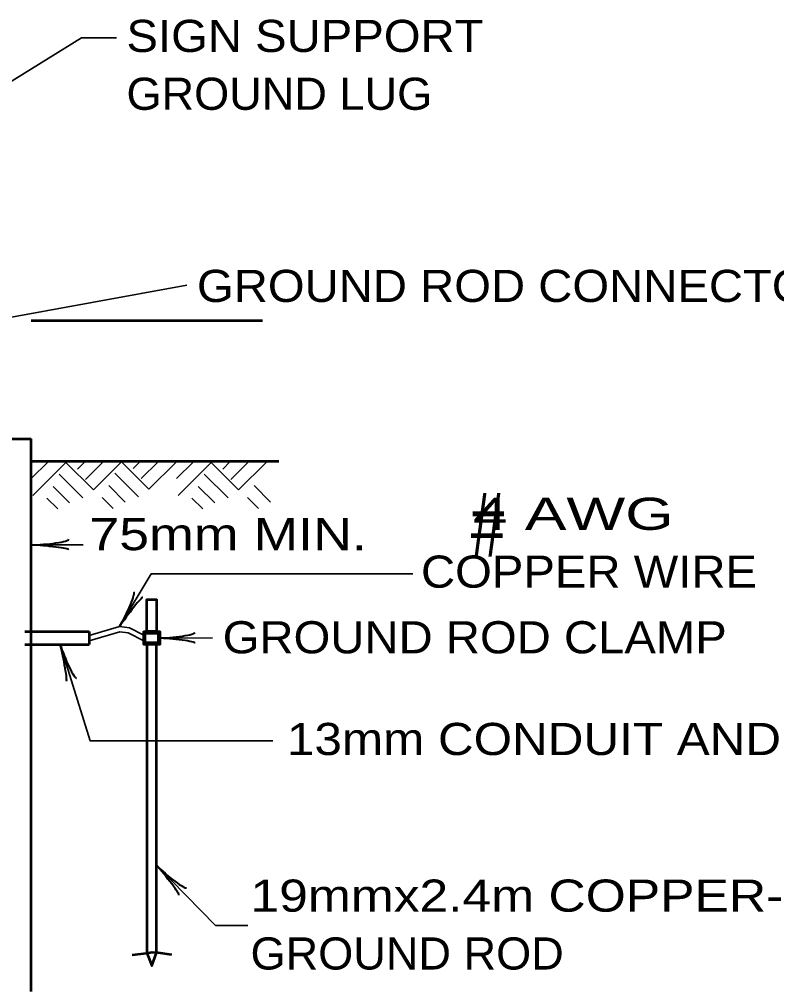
# Model space of a CAD drawing. Extents: x -111 to 744, y -77 to 467.
# Drawn here: x 250.1 to 320.8, y 162.4 to 252.8 of the extents above; entities that cross this region are included whole.
import ezdxf

# ---------------------------------------------------------------- set-up
doc = ezdxf.new("R2010")
doc.units = 0
doc.header["$LTSCALE"] = 1.2
doc.linetypes.add('LONG_DASHED', pattern=[7.5, 6, -1.5])
doc.layers.add('1', color=7, linetype='Continuous', lineweight=53)

msp = doc.modelspace()

# ---------------------------------------------------------------- linework, layer by layer
at = {"layer": '1', "lineweight": 35}
for p, q in [((234.019, 222.168), (265.782, 227.964)), ((252.823, 211.483), (251.239, 209.899)), ((254.527, 211.483), (251.383, 208.339)), ((254.407, 211.483), (257.047, 208.843)), ((256.231, 211.483), (255.559, 210.787)), ((257.959, 211.483), (256.303, 209.827)), ((259.663, 211.483), (257.047, 208.843)), ((259.663, 211.483), (262.231, 208.915)), ((261.367, 211.483), (260.743, 210.859)), ((263.095, 211.483), (261.511, 209.899)), ((264.799, 211.483), (262.231, 208.915)), ((266.383, 211.483), (264.799, 209.899)), ((268.087, 211.483), (264.943, 208.339)), ((267.967, 211.483), (270.607, 208.843)), ((269.791, 211.483), (269.119, 210.787)), ((271.519, 211.483), (269.863, 209.827)), ((273.223, 211.483), (270.607, 208.843)), ((253.831, 210.331), (256.063, 208.123)), ((259.039, 210.403), (261.247, 208.195)), ((267.391, 210.331), (269.623, 208.123)), ((253.279, 209.179), (254.815, 207.643)), ((258.487, 209.251), (260.023, 207.715)), ((266.839, 209.179), (268.375, 207.643)), ((272.047, 209.251), (273.583, 207.715)), ((252.679, 208.075), (253.711, 207.067)), ((257.863, 208.147), (258.895, 207.115)), ((266.239, 208.075), (267.271, 207.067)), ((271.423, 208.147), (272.455, 207.115)), ((251.289, 203.717), (256.089, 203.717)), ((263.089, 195.018), (268.156, 195.032))]:
    msp.add_line(p, q, dxfattribs=at)
at = {"layer": '1'}
for p, q in [((251.239, 224.648), (272.839, 224.648)), ((251.239, 162.031), (251.239, 213.618)), ((251.239, 211.531), (274.358, 211.531)), ((251.239, 195.618), (256.639, 195.618)), ((256.639, 195.618), (256.639, 194.418)), ((261.739, 195.603), (261.754, 195.618)), ((261.739, 195.586), (261.771, 195.618)), ((261.739, 195.569), (261.788, 195.618)), ((261.739, 195.552), (261.805, 195.618)), ((261.739, 195.535), (261.822, 195.618)), ((261.739, 195.518), (261.839, 195.618)), ((261.739, 195.501), (261.856, 195.618)), ((261.739, 195.484), (261.873, 195.618)), ((261.739, 195.467), (261.89, 195.618)), ((261.739, 195.45), (261.907, 195.618)), ((261.739, 195.433), (261.924, 195.618)), ((261.739, 195.416), (261.941, 195.618)), ((261.739, 195.399), (261.958, 195.618)), ((261.739, 195.382), (261.975, 195.618)), ((261.739, 195.365), (261.992, 195.618)), ((261.739, 195.348), (262.009, 195.618)), ((261.739, 195.331), (262.026, 195.618)), ((261.739, 195.314), (261.889, 195.464)), ((261.739, 195.297), (261.889, 195.447)), ((261.739, 195.28), (261.889, 195.43)), ((261.739, 195.263), (261.889, 195.413)), ((261.739, 195.246), (261.889, 195.396)), ((261.739, 195.229), (261.889, 195.379)), ((261.739, 195.213), (261.889, 195.363)), ((261.739, 195.196), (261.889, 195.346)), ((261.739, 195.179), (261.889, 195.329)), ((261.739, 195.162), (261.889, 195.312)), ((261.739, 195.145), (261.889, 195.295)), ((261.739, 195.128), (261.889, 195.278)), ((261.739, 195.111), (261.889, 195.261)), ((261.889, 195.468), (262.039, 195.468)), ((261.893, 195.468), (262.043, 195.618)), ((261.91, 195.468), (262.06, 195.618)), ((261.927, 195.468), (262.077, 195.618)), ((261.944, 195.468), (262.094, 195.618)), ((261.961, 195.468), (262.111, 195.618)), ((261.978, 195.468), (262.128, 195.618)), ((261.995, 195.468), (262.145, 195.618)), ((262.012, 195.468), (262.162, 195.618)), ((262.029, 195.468), (262.179, 195.618)), ((262.039, 195.618), (262.939, 195.618)), ((262.046, 195.468), (262.196, 195.618)), ((262.062, 195.468), (262.213, 195.618)), ((262.079, 195.468), (262.23, 195.618)), ((262.096, 195.468), (262.247, 195.618)), ((262.113, 195.468), (262.263, 195.618)), ((262.13, 195.468), (262.28, 195.618)), ((262.147, 195.468), (262.297, 195.618)), ((262.164, 195.468), (262.314, 195.618)), ((262.181, 195.468), (262.331, 195.618)), ((262.198, 195.468), (262.348, 195.618)), ((262.215, 195.468), (262.365, 195.618)), ((262.232, 195.468), (262.382, 195.618)), ((262.249, 195.468), (262.399, 195.618)), ((262.266, 195.468), (262.416, 195.618)), ((262.283, 195.468), (262.433, 195.618)), ((262.3, 195.468), (262.45, 195.618)), ((262.317, 195.468), (262.467, 195.618)), ((262.334, 195.468), (262.484, 195.618)), ((262.351, 195.468), (262.501, 195.618)), ((262.368, 195.468), (262.518, 195.618)), ((262.385, 195.468), (262.535, 195.618)), ((262.402, 195.468), (262.552, 195.618)), ((262.419, 195.468), (262.569, 195.618)), ((262.436, 195.468), (262.586, 195.618)), ((262.453, 195.468), (262.603, 195.618)), ((262.47, 195.468), (262.62, 195.618)), ((262.487, 195.468), (262.637, 195.618)), ((262.504, 195.468), (262.654, 195.618)), ((262.521, 195.468), (262.671, 195.618)), ((262.538, 195.468), (262.688, 195.618)), ((262.555, 195.468), (262.705, 195.618)), ((262.572, 195.468), (262.722, 195.618)), ((262.589, 195.468), (262.739, 195.618)), ((262.606, 195.468), (262.756, 195.618)), ((262.623, 195.468), (262.773, 195.618)), ((262.639, 195.468), (262.79, 195.618)), ((262.656, 195.468), (262.807, 195.618)), ((262.673, 195.468), (262.824, 195.618)), ((262.69, 195.468), (262.84, 195.618)), ((262.707, 195.468), (262.857, 195.618)), ((262.724, 195.468), (262.874, 195.618)), ((262.741, 195.468), (262.891, 195.618)), ((262.758, 195.468), (262.908, 195.618)), ((262.775, 195.468), (262.925, 195.618)), ((262.792, 195.468), (262.942, 195.618)), ((262.809, 195.468), (262.959, 195.618)), ((262.826, 195.468), (262.976, 195.618)), ((262.843, 195.468), (262.993, 195.618)), ((262.86, 195.468), (263.01, 195.618)), ((262.877, 195.468), (263.027, 195.618)), ((262.894, 195.468), (263.044, 195.618)), ((262.911, 195.468), (263.061, 195.618)), ((262.928, 195.468), (263.078, 195.618)), ((262.945, 195.468), (263.095, 195.618)), ((262.962, 195.468), (263.112, 195.618)), ((262.979, 195.468), (263.129, 195.618)), ((262.996, 195.468), (263.146, 195.618)), ((263.013, 195.468), (263.163, 195.618)), ((263.03, 195.468), (263.18, 195.618)), ((263.047, 195.468), (263.197, 195.618)), ((263.064, 195.468), (263.214, 195.618)), ((263.081, 195.468), (263.231, 195.618)), ((263.089, 195.459), (263.239, 195.609)), ((263.089, 195.442), (263.239, 195.592)), ((263.089, 195.425), (263.239, 195.575)), ((263.089, 195.409), (263.239, 195.559)), ((263.089, 195.392), (263.239, 195.542)), ((263.089, 195.375), (263.239, 195.525)), ((263.089, 195.358), (263.239, 195.508)), ((263.089, 195.341), (263.239, 195.491)), ((263.089, 195.324), (263.239, 195.474)), ((263.089, 195.307), (263.239, 195.457)), ((263.089, 195.29), (263.239, 195.44)), ((263.089, 195.273), (263.239, 195.423)), ((263.089, 195.256), (263.239, 195.406)), ((263.089, 195.239), (263.239, 195.389)), ((263.089, 195.222), (263.239, 195.372)), ((263.089, 195.205), (263.239, 195.355)), ((263.089, 195.188), (263.239, 195.338)), ((263.089, 195.171), (263.239, 195.321)), ((263.089, 195.154), (263.239, 195.304)), ((263.089, 195.137), (263.239, 195.287)), ((263.089, 195.12), (263.239, 195.27)), ((263.089, 195.103), (263.239, 195.253)), ((251.239, 194.418), (256.639, 194.418)), ((261.739, 195.094), (261.889, 195.244)), ((261.739, 195.077), (261.889, 195.227)), ((261.739, 195.06), (261.889, 195.21)), ((261.739, 195.043), (261.889, 195.193)), ((261.739, 195.026), (261.889, 195.176)), ((261.739, 195.009), (261.889, 195.159)), ((261.739, 194.992), (261.889, 195.142)), ((261.739, 194.975), (261.889, 195.125)), ((261.739, 194.958), (261.889, 195.108)), ((261.739, 194.941), (261.889, 195.091)), ((261.739, 194.924), (261.889, 195.074)), ((261.739, 194.907), (261.889, 195.057)), ((261.739, 194.89), (261.889, 195.04)), ((261.739, 194.873), (261.889, 195.023)), ((261.739, 194.856), (261.889, 195.006)), ((261.739, 194.839), (261.889, 194.989)), ((261.739, 194.822), (261.889, 194.972)), ((261.739, 194.805), (261.889, 194.955)), ((261.739, 194.788), (261.889, 194.938)), ((261.739, 194.771), (261.889, 194.921)), ((261.739, 194.754), (261.889, 194.904)), ((261.739, 194.737), (261.889, 194.887)), ((261.739, 194.72), (261.889, 194.87)), ((261.739, 194.703), (261.889, 194.853)), ((261.739, 194.686), (261.889, 194.836)), ((261.739, 194.669), (261.889, 194.819)), ((261.739, 194.652), (261.889, 194.802)), ((261.739, 194.636), (261.889, 194.786)), ((261.739, 194.619), (261.889, 194.769)), ((261.739, 194.602), (261.889, 194.752)), ((261.739, 194.585), (261.889, 194.735)), ((261.739, 194.568), (261.889, 194.718)), ((261.739, 194.551), (261.889, 194.701)), ((261.739, 194.534), (261.889, 194.684)), ((261.739, 194.517), (261.889, 194.667)), ((261.739, 194.5), (261.889, 194.65)), ((261.739, 194.483), (261.889, 194.633)), ((261.739, 194.466), (261.889, 194.616)), ((261.739, 194.449), (261.889, 194.599)), ((261.739, 194.432), (261.889, 194.582)), ((261.742, 194.418), (261.892, 194.568)), ((261.759, 194.418), (261.909, 194.568)), ((261.776, 194.418), (261.926, 194.568)), ((261.793, 194.418), (261.943, 194.568)), ((261.81, 194.418), (261.96, 194.568)), ((261.827, 194.418), (261.977, 194.568)), ((261.844, 194.418), (261.994, 194.568)), ((261.861, 194.418), (262.011, 194.568)), ((261.878, 194.418), (262.028, 194.568)), ((261.895, 194.418), (262.045, 194.568)), ((261.912, 194.418), (262.062, 194.568)), ((261.929, 194.418), (262.079, 194.568)), ((261.946, 194.418), (262.096, 194.568)), ((261.963, 194.418), (262.113, 194.568)), ((261.98, 194.418), (262.13, 194.568)), ((261.997, 194.418), (262.147, 194.568)), ((262.014, 194.418), (262.164, 194.568)), ((262.031, 194.418), (262.181, 194.568)), ((262.048, 194.418), (262.198, 194.568)), ((262.065, 194.418), (262.215, 194.568)), ((262.082, 194.418), (262.232, 194.568)), ((262.099, 194.418), (262.249, 194.568)), ((262.116, 194.418), (262.266, 194.568)), ((262.133, 194.418), (262.283, 194.568)), ((262.149, 194.418), (262.3, 194.568)), ((262.166, 194.418), (262.317, 194.568)), ((262.184, 194.418), (262.334, 194.568)), ((262.201, 194.418), (262.351, 194.568)), ((262.217, 194.418), (262.367, 194.568)), ((262.234, 194.418), (262.384, 194.568)), ((262.251, 194.418), (262.401, 194.568)), ((262.268, 194.418), (262.418, 194.568)), ((262.285, 194.418), (262.435, 194.568)), ((262.302, 194.418), (262.452, 194.568)), ((262.319, 194.418), (262.469, 194.568)), ((262.336, 194.418), (262.486, 194.568)), ((262.353, 194.418), (262.503, 194.568)), ((262.37, 194.418), (262.52, 194.568)), ((262.387, 194.418), (262.537, 194.568)), ((262.404, 194.418), (262.554, 194.568)), ((262.421, 194.418), (262.571, 194.568)), ((262.438, 194.418), (262.588, 194.568)), ((262.455, 194.418), (262.605, 194.568)), ((262.472, 194.418), (262.622, 194.568)), ((262.489, 194.418), (262.639, 194.568)), ((262.506, 194.418), (262.656, 194.568)), ((262.523, 194.418), (262.673, 194.568)), ((262.54, 194.418), (262.69, 194.568)), ((262.557, 194.418), (262.707, 194.568)), ((262.574, 194.418), (262.724, 194.568)), ((262.591, 194.418), (262.741, 194.568)), ((262.608, 194.418), (262.758, 194.568)), ((262.625, 194.418), (262.775, 194.568)), ((262.642, 194.418), (262.792, 194.568)), ((262.659, 194.418), (262.809, 194.568)), ((262.676, 194.418), (262.826, 194.568)), ((262.693, 194.418), (262.843, 194.568)), ((262.71, 194.418), (262.86, 194.568)), ((262.726, 194.418), (262.877, 194.568)), ((262.744, 194.418), (262.894, 194.568)), ((262.761, 194.418), (262.911, 194.568)), ((262.778, 194.418), (262.928, 194.568)), ((262.794, 194.418), (262.944, 194.568)), ((262.811, 194.418), (262.961, 194.568)), ((262.828, 194.418), (262.978, 194.568)), ((262.845, 194.418), (262.995, 194.568)), ((262.862, 194.418), (263.012, 194.568)), ((262.879, 194.418), (263.029, 194.568)), ((262.896, 194.418), (263.046, 194.568)), ((262.913, 194.418), (263.063, 194.568)), ((262.93, 194.418), (263.08, 194.568)), ((262.947, 194.418), (263.239, 194.71)), ((262.964, 194.418), (263.239, 194.693)), ((262.981, 194.418), (263.239, 194.676)), ((262.998, 194.418), (263.239, 194.659)), ((263.015, 194.418), (263.239, 194.642)), ((263.032, 194.418), (263.239, 194.625)), ((263.049, 194.418), (263.239, 194.608)), ((263.066, 194.418), (263.239, 194.591)), ((263.083, 194.418), (263.239, 194.574)), ((263.089, 195.086), (263.239, 195.236)), ((263.089, 195.069), (263.239, 195.219)), ((263.089, 195.052), (263.239, 195.202)), ((263.089, 195.035), (263.239, 195.185)), ((263.089, 195.018), (263.239, 195.168)), ((263.089, 195.001), (263.239, 195.151)), ((263.089, 194.984), (263.239, 195.134)), ((263.089, 194.967), (263.239, 195.117)), ((263.089, 194.95), (263.239, 195.1)), ((263.089, 194.933), (263.239, 195.083)), ((263.089, 194.916), (263.239, 195.066)), ((263.089, 194.899), (263.239, 195.049)), ((263.089, 194.882), (263.239, 195.032)), ((263.089, 194.865), (263.239, 195.015)), ((263.089, 194.848), (263.239, 194.998)), ((263.089, 194.832), (263.239, 194.982)), ((263.089, 194.815), (263.239, 194.965)), ((263.089, 194.798), (263.239, 194.948)), ((263.089, 194.781), (263.239, 194.931)), ((263.089, 194.764), (263.239, 194.914)), ((263.089, 194.747), (263.239, 194.897)), ((263.089, 194.73), (263.239, 194.88)), ((263.089, 194.713), (263.239, 194.863)), ((263.089, 194.696), (263.239, 194.846)), ((263.089, 194.679), (263.239, 194.829)), ((263.089, 194.662), (263.239, 194.812)), ((263.089, 194.645), (263.239, 194.795)), ((263.089, 194.628), (263.239, 194.778)), ((263.089, 194.611), (263.239, 194.761)), ((263.089, 194.594), (263.239, 194.744)), ((263.089, 194.577), (263.239, 194.727)), ((263.1, 194.418), (263.239, 194.557)), ((263.117, 194.418), (263.239, 194.54)), ((263.134, 194.418), (263.239, 194.523)), ((263.151, 194.418), (263.239, 194.506)), ((263.168, 194.418), (263.239, 194.489)), ((263.185, 194.418), (263.239, 194.472)), ((263.202, 194.418), (263.239, 194.455)), ((263.219, 194.418), (263.239, 194.438)), ((263.236, 194.418), (263.239, 194.421))]:
    msp.add_line(p, q, dxfattribs=at)
at = {"layer": '1', "linetype": 'LONG_DASHED'}
for p, q in [((241.639, 195.618), (251.239, 195.618)), ((241.639, 194.418), (251.239, 194.418))]:
    msp.add_line(p, q, dxfattribs=at)
at = {"layer": '1', "lineweight": 35}
for points in [[(241.227, 241.951), (255.92, 251.066), (259.202, 251.066)], [(259.484, 196.091), (262.45, 201.009), (286.858, 201.009)], [(256.639, 195.268), (259.484, 196.091), (260.421, 195.957), (261.739, 195.287), (261.739, 194.749)], [(261.739, 194.749), (260.275, 195.493), (259.518, 195.601), (256.639, 194.768), (256.639, 195.268)], [(253.939, 194.418), (256.743, 185.418), (273.8, 185.418)], [(262.939, 173.803), (268.447, 168.197), (271.449, 168.197)]]:
    msp.add_lwpolyline(points, dxfattribs=at)
at = {"layer": '1'}
for points in [[(214.639, 162.031), (214.639, 213.618), (251.239, 213.618)], [(260.652, 165.45), (261.992, 165.608), (262.525, 165.695), (263.044, 165.651), (264.341, 165.478)]]:
    msp.add_lwpolyline(points, dxfattribs=at)
for points in [[(262.039, 195.618), (262.039, 198.618), (262.939, 198.618), (262.939, 195.618)], [(261.739, 195.618), (262.039, 195.618), (262.939, 195.618), (263.239, 195.618), (263.239, 194.418), (262.939, 194.418), (262.039, 194.418), (261.739, 194.418), (261.739, 194.749), (261.739, 195.287)], [(261.889, 195.468), (262.939, 195.468), (263.089, 195.468), (263.089, 194.568), (262.939, 194.568), (261.889, 194.568), (261.889, 194.749), (261.889, 195.287)], [(262.939, 165.618), (262.939, 194.418), (262.039, 194.418), (262.039, 165.618), (262.489, 164.418)]]:
    msp.add_lwpolyline(points, close=True, dxfattribs=at)
at = {"layer": '1', "lineweight": 40}
for centre, major_axis, ratio, start_param, end_param in [((252.633, 203.463), (-2.108, 0.211), 0.07063, 3.140715, 5.41811), ((252.633, 203.463), (-2.108, 0.211), 0.07063, 3.140715, 5.41811), ((252.598, 204.049), (-2.143, -0.187), 0.122415, 0.896353, 3.141593), ((252.598, 204.049), (-2.143, -0.187), 0.122415, 0.896353, 3.141593), ((259.876, 197.383), (-0.946, -1.932), 0.122415, 0.896353, 3.141593), ((259.876, 197.383), (-0.946, -1.932), 0.122415, 0.896353, 3.141593), ((260.396, 197.111), (1.269, 1.696), 0.07063, 6.282307, 8.559703), ((260.396, 197.111), (1.269, 1.696), 0.07063, 6.282307, 8.559703), ((264.398, 195.353), (-2.142, -0.193), 0.122415, 0.896353, 3.141593), ((254.097, 193.058), (0.426, -2.075), 0.07063, 6.282307, 8.559703), ((254.645, 193.266), (-0.816, 1.99), 0.122415, 0.896353, 3.141593), ((264.435, 194.768), (-2.108, 0.205), 0.07063, 3.140715, 5.41811), ((263.701, 172.665), (-1.327, 1.651), 0.07063, 3.140715, 5.41811), ((263.701, 172.665), (-1.327, 1.651), 0.07063, 3.140715, 5.41811), ((264.094, 173.101), (-1.635, 1.397), 0.122415, 0.896353, 3.141593), ((264.094, 173.101), (-1.635, 1.397), 0.122415, 0.896353, 3.141593)]:
    msp.add_ellipse(centre, major_axis=major_axis, ratio=ratio, start_param=start_param, end_param=end_param, dxfattribs=at)

# ---------------------------------------------------------------- texts
at = {"layer": '1'}
for s, height, width, p in [('SIGN SUPPORT', 3, 1.1, (260.13, 249.73)), ('GROUND LUG', 3, 1.05, (260.13, 244.33)), ('GROUND ROD CONNECTOR', 3, 1.1, (266.713, 226.392)), ('#', 6, 0.7, (292.292, 202.607)), ('   4 AWG', 3, 1.45, (287.634, 205.117)), ('75mm MIN.', 3, 1.25, (256.665, 203.22)), ('COPPER WIRE', 3, 1.1, (287.634, 199.717)), ('GROUND ROD CLAMP', 3, 1.1, (269.115, 193.589)), ('13mm CONDUIT AND END BUSHING', 3, 1.15, (275.121, 184.096)), ('19mmx2.4m COPPER-CLAD', 3, 1.2, (271.716, 169.472)), ('GROUND ROD', 3, 1.05, (271.716, 164.072))]:
    msp.add_text(s, height=height, dxfattribs=dict(at, width=width)).set_placement(p)

doc.saveas('drawing.dxf')
